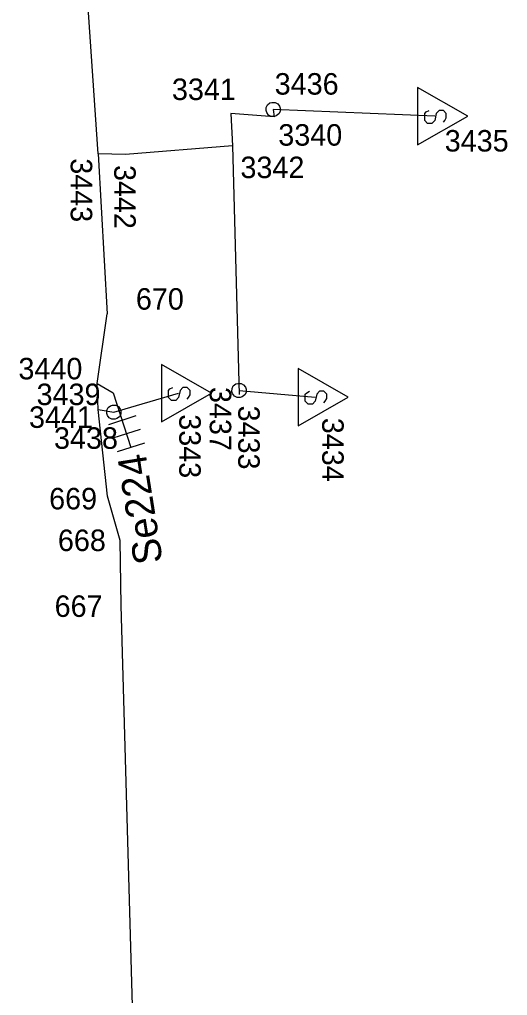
# Model space of a CAD drawing. Extents: x -535557 to -534097, y -1142175 to -1136716.
# Drawn here: x -534482.55 to -534465.52, y -1140940.58 to -1140906.51 of the extents above; entities that cross this region are included whole.
import ezdxf

# ---------------------------------------------------------------- set-up
doc = ezdxf.new("R2010")
doc.units = 0
doc.layers.add('Default', color=7, linetype='Continuous')
doc.layers.add('SS_SZDC', color=7, linetype='Continuous')

# ---------------------------------------------------------------- blocks, each defined once
blk = doc.blocks.new('POINT_DISPLAY')
at = {"layer": 'Default'}
blk.add_line((0, 0), (0, 0), dxfattribs=at)

msp = doc.modelspace()

# ---------------------------------------------------------------- linework, layer by layer
at = {"layer": 'SS_SZDC'}
for p, q in [((-534479.8, -1140911.2), (-534480.71, -1140898.139)), ((-534468.66, -1140908.889), (-534468.66, -1140910.889)), ((-534466.91, -1140909.889), (-534468.66, -1140908.889)), ((-534473.81, -1140909.425), (-534473.742, -1140909.403)), ((-534473.742, -1140909.403), (-534473.631, -1140909.404)), ((-534473.631, -1140909.404), (-534473.541, -1140909.449)), ((-534473.946, -1140909.692), (-534473.945, -1140909.581)), ((-534473.924, -1140909.76), (-534473.946, -1140909.692)), ((-534473.945, -1140909.581), (-534473.9, -1140909.491)), ((-534473.9, -1140909.491), (-534473.81, -1140909.425)), ((-534468.06, -1140909.889), (-534473.699, -1140909.649)), ((-534473.699, -1140909.649), (-534473.67, -1140909.909)), ((-534473.541, -1140909.449), (-534473.475, -1140909.539)), ((-534473.454, -1140909.718), (-534473.499, -1140909.808)), ((-534473.475, -1140909.539), (-534473.453, -1140909.607)), ((-534473.453, -1140909.607), (-534473.454, -1140909.718)), ((-534468.41, -1140909.789), (-534468.36, -1140909.739)), ((-534468.36, -1140909.739), (-534468.26, -1140909.689)), ((-534467.91, -1140909.689), (-534468.01, -1140909.789)), ((-534467.76, -1140909.689), (-534467.91, -1140909.689)), ((-534467.66, -1140909.789), (-534467.76, -1140909.689)), ((-534473.67, -1140909.909), (-534475.18, -1140909.79)), ((-534475.18, -1140909.79), (-534475.119, -1140910.92)), ((-534473.858, -1140909.85), (-534473.924, -1140909.76)), ((-534473.768, -1140909.895), (-534473.858, -1140909.85)), ((-534473.657, -1140909.896), (-534473.768, -1140909.895)), ((-534473.589, -1140909.874), (-534473.657, -1140909.896)), ((-534473.499, -1140909.808), (-534473.589, -1140909.874)), ((-534468.66, -1140910.889), (-534466.91, -1140909.889)), ((-534468.41, -1140910.039), (-534468.41, -1140909.789)), ((-534468.31, -1140910.139), (-534468.41, -1140910.039)), ((-534468.06, -1140910.039), (-534468.16, -1140910.139)), ((-534468.01, -1140909.789), (-534468.06, -1140910.039)), ((-534467.76, -1140910.089), (-534467.71, -1140910.039)), ((-534467.71, -1140910.039), (-534467.66, -1140909.939)), ((-534467.66, -1140909.939), (-534467.66, -1140909.789)), ((-534468.16, -1140910.139), (-534468.31, -1140910.139)), ((-534475.119, -1140910.92), (-534478.85, -1140911.229)), ((-534475.119, -1140910.92), (-534474.89, -1140919.6)), ((-534478.85, -1140911.229), (-534479.8, -1140911.2)), ((-534479.8, -1140911.2), (-534479.489, -1140916.79)), ((-534479.84, -1140919.219), (-534479.489, -1140916.79)), ((-534477.599, -1140918.559), (-534477.599, -1140920.559)), ((-534475.849, -1140919.559), (-534477.599, -1140918.559)), ((-534472.829, -1140918.69), (-534472.829, -1140920.69)), ((-534471.079, -1140919.69), (-534472.829, -1140918.69)), ((-534479.8, -1140920.12), (-534479.84, -1140919.219)), ((-534479.84, -1140919.219), (-534479.279, -1140919.549)), ((-534475.09, -1140919.301), (-534475, -1140919.235)), ((-534475, -1140919.235), (-534474.932, -1140919.213)), ((-534474.932, -1140919.213), (-534474.821, -1140919.214)), ((-534474.821, -1140919.214), (-534474.731, -1140919.259)), ((-534474.731, -1140919.259), (-534474.665, -1140919.349)), ((-534479.279, -1140919.549), (-534478.661, -1140921.452)), ((-534479.26, -1140920.219), (-534477, -1140919.559)), ((-534477.599, -1140920.559), (-534475.849, -1140919.559)), ((-534477.349, -1140919.459), (-534477.3, -1140919.409)), ((-534477.349, -1140919.709), (-534477.349, -1140919.459)), ((-534477.3, -1140919.409), (-534477.199, -1140919.359)), ((-534476.949, -1140919.459), (-534477, -1140919.709)), ((-534476.849, -1140919.359), (-534476.949, -1140919.459)), ((-534476.699, -1140919.359), (-534476.849, -1140919.359)), ((-534476.599, -1140919.459), (-534476.699, -1140919.359)), ((-534476.65, -1140919.709), (-534476.599, -1140919.609)), ((-534476.599, -1140919.609), (-534476.599, -1140919.459)), ((-534475.136, -1140919.502), (-534475.135, -1140919.391)), ((-534475.114, -1140919.57), (-534475.136, -1140919.502)), ((-534475.135, -1140919.391), (-534475.09, -1140919.301)), ((-534475.048, -1140919.66), (-534475.114, -1140919.57)), ((-534474.89, -1140919.459), (-534474.89, -1140919.6)), ((-534474.89, -1140919.459), (-534472.229, -1140919.69)), ((-534474.689, -1140919.618), (-534474.779, -1140919.684)), ((-534474.644, -1140919.528), (-534474.689, -1140919.618)), ((-534474.665, -1140919.349), (-534474.643, -1140919.417)), ((-534474.643, -1140919.417), (-534474.644, -1140919.528)), ((-534472.579, -1140919.59), (-534472.529, -1140919.54)), ((-534472.579, -1140919.84), (-534472.579, -1140919.59)), ((-534472.529, -1140919.54), (-534472.429, -1140919.49)), ((-534472.179, -1140919.59), (-534472.229, -1140919.84)), ((-534472.079, -1140919.49), (-534472.179, -1140919.59)), ((-534471.929, -1140919.49), (-534472.079, -1140919.49)), ((-534471.829, -1140919.59), (-534471.929, -1140919.49)), ((-534471.829, -1140919.74), (-534471.829, -1140919.59)), ((-534477.25, -1140919.809), (-534477.349, -1140919.709)), ((-534477.099, -1140919.809), (-534477.25, -1140919.809)), ((-534477, -1140919.709), (-534477.099, -1140919.809)), ((-534476.699, -1140919.759), (-534476.65, -1140919.709)), ((-534474.958, -1140919.705), (-534475.048, -1140919.66)), ((-534474.847, -1140919.706), (-534474.958, -1140919.705)), ((-534474.779, -1140919.684), (-534474.847, -1140919.706)), ((-534472.829, -1140920.69), (-534471.079, -1140919.69)), ((-534472.479, -1140919.94), (-534472.579, -1140919.84)), ((-534472.329, -1140919.94), (-534472.479, -1140919.94)), ((-534472.229, -1140919.84), (-534472.329, -1140919.94)), ((-534471.929, -1140919.89), (-534471.879, -1140919.84)), ((-534471.879, -1140919.84), (-534471.829, -1140919.74)), ((-534479.479, -1140923.149), (-534479.8, -1140920.12)), ((-534479.8, -1140920.12), (-534479.26, -1140920.219)), ((-534479.506, -1140920.262), (-534479.505, -1140920.151)), ((-534479.484, -1140920.33), (-534479.506, -1140920.262)), ((-534479.505, -1140920.151), (-534479.46, -1140920.061)), ((-534479.46, -1140920.061), (-534479.37, -1140919.995)), ((-534479.37, -1140919.995), (-534479.302, -1140919.973)), ((-534479.302, -1140919.973), (-534479.191, -1140919.974)), ((-534479.191, -1140919.974), (-534479.101, -1140920.019)), ((-534479.101, -1140920.019), (-534479.035, -1140920.109)), ((-534479.014, -1140920.288), (-534479.059, -1140920.378)), ((-534479.035, -1140920.109), (-534479.013, -1140920.177)), ((-534479.013, -1140920.177), (-534479.014, -1140920.288)), ((-534479.418, -1140920.42), (-534479.484, -1140920.33)), ((-534478.495, -1140920.346), (-534479.446, -1140920.655)), ((-534479.328, -1140920.465), (-534479.418, -1140920.42)), ((-534479.217, -1140920.466), (-534479.328, -1140920.465)), ((-534479.149, -1140920.444), (-534479.217, -1140920.466)), ((-534479.059, -1140920.378), (-534479.149, -1140920.444)), ((-534478.34, -1140920.822), (-534479.292, -1140921.131)), ((-534478.186, -1140921.297), (-534479.137, -1140921.606)), ((-534479.039, -1140924.7), (-534479.479, -1140923.149)), ((-534479, -1140926.969), (-534479.039, -1140924.7)), ((-534478.399, -1140948.52), (-534479, -1140926.969))]:
    msp.add_line(p, q, dxfattribs=at)

# ---------------------------------------------------------------- block references
for p in [(-534473.699, -1140909.649), (-534473.699, -1140909.649), (-534475.18, -1140909.79), (-534473.67, -1140909.909), (-534468.06, -1140909.889), (-534475.119, -1140910.92), (-534479.8, -1140911.2), (-534478.85, -1140911.229), (-534479.489, -1140916.79), (-534479.84, -1140919.219), (-534479.279, -1140919.549), (-534477, -1140919.559), (-534474.89, -1140919.459), (-534474.89, -1140919.459), (-534474.89, -1140919.6), (-534472.229, -1140919.69), (-534479.8, -1140920.12), (-534479.26, -1140920.219), (-534479.26, -1140920.219), (-534479.479, -1140923.149), (-534479.039, -1140924.7), (-534479, -1140926.969)]:
    msp.add_blockref('POINT_DISPLAY', p, dxfattribs=at)

# ---------------------------------------------------------------- texts
for s, p in [('3436', (-534473.646, -1140909.133)), ('3341', (-534477.231, -1140909.322)), ('3340', (-534473.52, -1140910.915)), ('3435', (-534467.713, -1140911.12)), ('3342', (-534474.841, -1140912.047)), ('670', (-534478.489, -1140916.64)), ('3440', (-534482.587, -1140919.073)), ('3439', (-534481.954, -1140919.971)), ('3441', (-534482.219, -1140920.767)), ('3438', (-534481.346, -1140921.497)), ('669', (-534481.516, -1140923.612)), ('668', (-534481.21, -1140925.067)), ('667', (-534481.324, -1140927.365))]:
    msp.add_text(s, height=0.75, dxfattribs=at).set_placement(p)
for s, height, rotation, p in [('3443', 0.75, 270, (-534480.763, -1140911.355)), ('3442', 0.75, 270, (-534479.245, -1140911.591)), ('3437', 0.75, 270, (-534475.912, -1140919.338)), ('3433', 0.75, 270, (-534474.918, -1140919.989)), ('3343', 0.75, 270, (-534476.976, -1140920.292)), ('3434', 0.75, 270, (-534471.989, -1140920.414)), ('Se224', 1, 99, (-534477.547, -1140925.442))]:
    msp.add_text(s, height=height, rotation=rotation, dxfattribs=at).set_placement(p)

doc.saveas('drawing.dxf')
